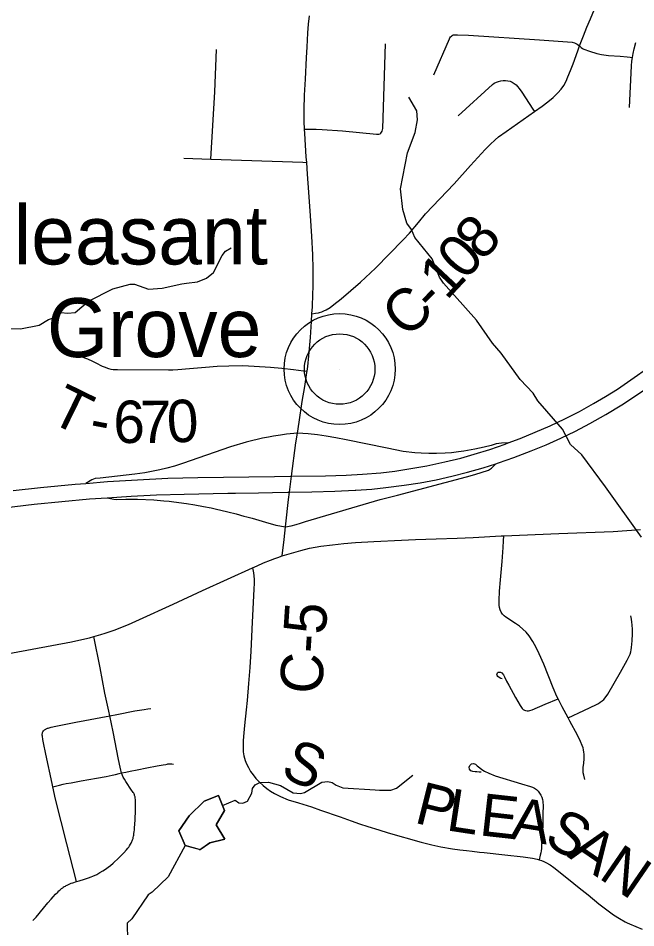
# Model space of a CAD drawing. Extents: x 0 to 34, y 0 to 22.
# Drawn here: x 2.781 to 3.609, y 15.425 to 16.645 of the extents above; entities that cross this region are included whole.
import ezdxf

# ---------------------------------------------------------------- set-up
doc = ezdxf.new("R2010")
doc.units = 0
for name, color, linetype in [('GM_X_County_Road', 7, 'Continuous'), ('GM_X_County_Road_Text', 7, 'Continuous'), ('GM_X_Interchange_Ramps', 7, 'Continuous'), ('GM_X_Interstate_Route', 7, 'Continuous'), ('GM_X_Minor_Lake', 7, 'Continuous'), ('GM_X_Minor_River', 7, 'Continuous'), ('GM_X_State_Route', 7, 'Continuous'), ('GM_X_Township_Road', 7, 'Continuous'), ('GM_X_Township_Road_Text', 7, 'Continuous'), ('GM_X_Unincorporated', 7, 'Continuous'), ('GM_X_Unincorporated_Location', 7, 'Continuous'), ('GM_X_Unincorporated_Text', 7, 'Continuous'), ('GM_X_US_Route', 7, 'Continuous')]:
    doc.layers.add(name, color=color, linetype=linetype)

msp = doc.modelspace()

# ---------------------------------------------------------------- linework, layer by layer
at = {"layer": 'GM_X_County_Road'}
for points in [[(3.533, 16.6075), (3.5384, 16.6211), (3.5428, 16.6327), (3.5477, 16.644), (3.5534, 16.6568)], [(3.4726, 16.5196), (3.4829, 16.5269), (3.4908, 16.5327), (3.4977, 16.5382), (3.5042, 16.5447), (3.5086, 16.5496), (3.5121, 16.5545), (3.515, 16.5603), (3.5176, 16.566), (3.521, 16.5746), (3.5244, 16.5833), (3.5309, 16.6008), (3.533, 16.6075)], [(3.1745, 16.2485), (3.1793, 16.2491), (3.1834, 16.2497), (3.1847, 16.25), (3.1877, 16.2511), (3.1906, 16.2523), (3.1934, 16.2537), (3.1987, 16.257), (3.2038, 16.2607), (3.2136, 16.2684), (3.2266, 16.2796), (3.2395, 16.2908), (3.2597, 16.3097), (3.2968, 16.3473), (3.3051, 16.3565), (3.3171, 16.3708), (3.3268, 16.3824), (3.3458, 16.4026), (3.365, 16.4228), (3.3871, 16.4473), (3.4068, 16.4688), (3.4132, 16.4754), (3.4199, 16.4817), (3.4247, 16.4855), (3.4346, 16.4929), (3.4726, 16.5196)], [(3.0949, 15.9076), (3.0959, 15.9011), (3.0965, 15.8968), (3.0969, 15.8922), (3.0971, 15.8872), (3.0967, 15.8793), (3.0942, 15.8349), (3.0925, 15.7958), (3.0912, 15.7741), (3.0896, 15.7524), (3.0878, 15.7299), (3.0865, 15.7173), (3.0842, 15.6961), (3.083, 15.6866), (3.0822, 15.6762), (3.0821, 15.6655), (3.0823, 15.6611), (3.0832, 15.6555), (3.0848, 15.6493), (3.0866, 15.6447), (3.0892, 15.6398), (3.0923, 15.6346), (3.0955, 15.6303), (3.0994, 15.6253), (3.104, 15.6205), (3.1091, 15.6157), (3.1138, 15.6118), (3.1191, 15.6081), (3.1241, 15.605), (3.1324, 15.6009), (3.1427, 15.5968), (3.1566, 15.5925), (3.1738, 15.5871), (3.1859, 15.5829), (3.2124, 15.5736), (3.2269, 15.5686), (3.2382, 15.5646), (3.2494, 15.5607), (3.264, 15.5562), (3.2766, 15.5523), (3.321, 15.5399), (3.3353, 15.5363), (3.3472, 15.5336), (3.3629, 15.531), (3.3729, 15.5296), (3.3814, 15.5285), (3.3893, 15.5276), (3.3992, 15.5265), (3.4053, 15.5259), (3.4331, 15.523), (3.4578, 15.5202), (3.4701, 15.5182), (3.4762, 15.5169), (3.479, 15.5161)], [(3.479, 15.5161), (3.4823, 15.5151), (3.4852, 15.514), (3.4881, 15.5127), (3.4936, 15.5096), (3.4988, 15.506), (3.5182, 15.4904), (3.5327, 15.4788), (3.5448, 15.469), (3.5592, 15.4573), (3.5714, 15.4477), (3.5788, 15.4423), (3.5865, 15.4373), (3.5945, 15.4329), (3.5972, 15.4317), (3.6001, 15.4304), (3.6172, 15.4233)]]:
    msp.add_lwpolyline(points, dxfattribs=at)
at = {"layer": 'GM_X_Interchange_Ramps'}
for points in [[(3.155, 16.0883), (3.1402, 16.087), (3.1323, 16.0857), (3.1228, 16.0842), (3.1161, 16.083), (3.1082, 16.0814), (3.101, 16.0799), (3.095, 16.0784), (3.0864, 16.0762), (3.0655, 16.07), (3.0008, 16.0474), (2.9904, 16.0442), (2.9799, 16.0414), (2.9705, 16.0391), (2.9617, 16.0373), (2.9506, 16.0353), (2.9371, 16.0334), (2.8906, 16.0281), (2.8838, 16.0275), (2.8795, 16.0256), (2.8712, 16.021)], [(3.4374, 16.0751), (3.4284, 16.0749), (3.4216, 16.0738), (3.4145, 16.0718), (3.4052, 16.0694), (3.3929, 16.0668), (3.3781, 16.0642), (3.3708, 16.0632), (3.3617, 16.0621), (3.3531, 16.0614), (3.3414, 16.061), (3.331, 16.061), (3.321, 16.0613), (3.3123, 16.0621), (3.2968, 16.0639), (3.2753, 16.068), (3.2204, 16.0795), (3.2066, 16.0821), (3.1937, 16.0843), (3.182, 16.0859), (3.1693, 16.0873), (3.155, 16.0883)], [(3.1388, 15.9628), (3.1467, 15.9639), (3.1535, 15.9658), (3.159, 15.9674), (3.1659, 15.9697), (3.2355, 15.9904), (3.266, 15.9992), (3.2891, 16.0052), (3.3817, 16.0297), (3.3927, 16.033), (3.4112, 16.0386), (3.4152, 16.0414), (3.421, 16.0472)], [(2.9001, 16.0016), (2.9091, 15.9998), (2.9128, 15.9993), (2.9248, 15.9996), (2.9407, 15.9996), (2.9623, 15.9987), (2.9761, 15.9977), (2.983, 15.997), (2.9894, 15.9962), (3.0064, 15.9938), (3.0173, 15.992), (3.0292, 15.9899), (3.0392, 15.9881), (3.0466, 15.9864), (3.0524, 15.985), (3.0615, 15.9829), (3.0727, 15.9801), (3.0833, 15.9772), (3.0873, 15.9761)], [(3.0873, 15.9761), (3.0943, 15.9742), (3.1124, 15.9689), (3.1261, 15.965), (3.1388, 15.9628)]]:
    msp.add_lwpolyline(points, dxfattribs=at)
at = {"layer": 'GM_X_Interstate_Route'}
for points in [[(2.7738, 16.0115), (2.8108, 16.0155), (2.8572, 16.0199), (2.8712, 16.021), (2.9005, 16.0233), (2.9408, 16.0259), (2.9812, 16.0278), (3.0215, 16.0288), (3.1241, 16.0303), (3.1472, 16.0306), (3.1924, 16.0311), (3.2204, 16.0319), (3.2421, 16.0332), (3.2669, 16.0353), (3.2855, 16.0375), (3.307, 16.0407), (3.3284, 16.0446), (3.3528, 16.0497), (3.3739, 16.0549), (3.3919, 16.0599), (3.4127, 16.0664), (3.4333, 16.0735), (3.4374, 16.0751), (3.4537, 16.0812), (3.4738, 16.0894), (3.4938, 16.0982), (3.5135, 16.1075), (3.5329, 16.1173), (3.552, 16.1279), (3.568, 16.1374), (3.5838, 16.1474), (3.6019, 16.1596), (3.6272, 16.1775)], [(3.2322, 16.0117), (3.2332, 16.0118), (3.2549, 16.0133), (3.2734, 16.0152), (3.298, 16.0184), (3.3195, 16.0218), (3.3408, 16.0258), (3.362, 16.0305), (3.383, 16.0358), (3.4039, 16.0418), (3.421, 16.0472), (3.4246, 16.0484), (3.4451, 16.0556), (3.4683, 16.0644), (3.4884, 16.0728), (3.5082, 16.0817), (3.5277, 16.0911), (3.5469, 16.1013), (3.5685, 16.1135), (3.5897, 16.1264), (3.608, 16.1382), (3.626, 16.1504)], [(2.6635, 15.9747), (2.6664, 15.9752), (2.7094, 15.9816), (2.7464, 15.9865), (2.8019, 15.993), (2.839, 15.9968), (2.8762, 16), (2.9001, 16.0016), (2.932, 16.0038), (2.9661, 16.0055), (3.0034, 16.0067), (3.0619, 16.0077)], [(3.0619, 16.0077), (3.0718, 16.0079), (3.1028, 16.0084), (3.1214, 16.0088), (3.1423, 16.0092)], [(3.1423, 16.0092), (3.1444, 16.0093), (3.1742, 16.0098), (3.2053, 16.0105), (3.2322, 16.0117)]]:
    msp.add_lwpolyline(points, dxfattribs=at)
at = {"layer": 'GM_X_Minor_Lake'}
for points in [[(3.0377, 15.5389), (3.0577, 15.5438), (3.046, 15.5632), (3.0573, 15.5822), (3.0494, 15.6023), (3.0301, 15.5947), (3.01, 15.5753), (2.996, 15.5552), (3.0044, 15.5355), (3.0247, 15.5299)], [(3.0237, 15.5302), (3.0044, 15.5355), (2.996, 15.5552), (3.01, 15.5753), (3.0301, 15.5947), (3.0494, 15.6023), (3.0573, 15.5822), (3.046, 15.5632), (3.0577, 15.5438), (3.0377, 15.5389), (3.0238, 15.5292)], [(3.0247, 15.5299), (3.0377, 15.5389)]]:
    msp.add_lwpolyline(points, dxfattribs=at)
at = {"layer": 'GM_X_Minor_River'}
for points in [[(3.6161, 15.9486), (3.5681, 16.0163), (3.5364, 16.0594), (3.5212, 16.073), (3.5102, 16.0938), (3.4774, 16.1316), (3.471, 16.1418), (3.4535, 16.1604), (3.4283, 16.1955), (3.4165, 16.2088), (3.3952, 16.2398), (3.3507, 16.2893), (3.3453, 16.2976), (3.3354, 16.3222), (3.3122, 16.3506), (3.3079, 16.3612), (3.3018, 16.3699), (3.2961, 16.3884), (3.2933, 16.4158), (3.3025, 16.464), (3.3126, 16.4914), (3.3159, 16.5085), (3.3151, 16.5203), (3.3044, 16.5388)], [(2.7703, 16.2288), (2.7839, 16.2281), (2.8089, 16.2332), (2.8213, 16.2409), (2.8307, 16.2439), (2.8383, 16.2501), (2.847, 16.249), (2.8572, 16.2502), (2.8749, 16.2654), (2.9077, 16.2816), (2.9308, 16.2881), (2.9364, 16.2882), (2.9554, 16.2814), (2.9735, 16.2827), (3, 16.2885), (3.0064, 16.2893), (3.0212, 16.2913), (3.0329, 16.2959), (3.0427, 16.3039), (3.0543, 16.3264), (3.0584, 16.3321), (3.066, 16.3367)], [(3.0545, 15.5892), (3.0716, 15.596), (3.0766, 15.5926), (3.0819, 15.5923), (3.0879, 15.5946), (3.0939, 15.6056), (3.0946, 15.6117), (3.0984, 15.6166), (3.1044, 15.6197), (3.1161, 15.6205), (3.1321, 15.6157), (3.1491, 15.6059), (3.159, 15.6052), (3.1643, 15.6064), (3.1876, 15.6202), (3.1956, 15.6213), (3.2016, 15.6199), (3.2069, 15.6161), (3.2157, 15.6127), (3.2592, 15.6099), (3.2652, 15.6096), (3.28, 15.6097), (3.2879, 15.6123), (3.3098, 15.6296)], [(3.0044, 15.5355), (2.9817, 15.4934), (2.9603, 15.4728), (2.955, 15.4693), (2.9332, 15.4369), (2.9268, 15.4312), (2.927, 15.408), (2.9213, 15.3966), (2.8733, 15.3227)]]:
    msp.add_lwpolyline(points, dxfattribs=at)
at = {"layer": 'GM_X_State_Route'}
for points in [[(3.155, 16.0883), (3.1572, 16.103), (3.1615, 16.1308), (3.1647, 16.151), (3.1663, 16.1602), (3.1677, 16.1697), (3.1679, 16.1712), (3.1688, 16.1777), (3.1702, 16.1918), (3.1723, 16.2164), (3.1738, 16.2381), (3.1745, 16.2485), (3.1751, 16.2576), (3.1756, 16.2747), (3.1759, 16.2845), (3.1759, 16.2957), (3.1759, 16.3086), (3.1756, 16.3274), (3.1743, 16.3524), (3.1725, 16.3796), (3.1701, 16.4113), (3.1685, 16.4354), (3.1674, 16.4514), (3.1668, 16.459), (3.1648, 16.49), (3.1646, 16.4957), (3.1642, 16.5061), (3.1639, 16.5223), (3.1643, 16.5414), (3.1656, 16.5628), (3.1672, 16.5915), (3.168, 16.6063), (3.1684, 16.6153), (3.1689, 16.6253), (3.1697, 16.6365), (3.171, 16.648)], [(3.1427, 15.9954), (3.1431, 15.9994), (3.1444, 16.0093), (3.1472, 16.0306), (3.153, 16.0754), (3.155, 16.0883)], [(3.1344, 15.9237), (3.137, 15.9457), (3.1388, 15.9628), (3.1397, 15.9707), (3.1427, 15.9954)], [(3.0949, 15.9076), (3.1011, 15.9105), (3.1097, 15.9142), (3.1188, 15.9179), (3.1246, 15.9202), (3.1288, 15.9217), (3.1344, 15.9237)], [(2.8822, 15.8155), (2.8915, 15.8181), (2.8973, 15.82), (2.9109, 15.8247), (2.9182, 15.8275), (2.9284, 15.8317), (2.9433, 15.8383), (2.9884, 15.859), (3.0278, 15.8771), (3.0949, 15.9076)], [(2.6781, 15.7771), (2.6907, 15.7789), (2.773, 15.7937), (2.8522, 15.8086), (2.862, 15.8106), (2.8764, 15.814), (2.8822, 15.8155)]]:
    msp.add_lwpolyline(points, dxfattribs=at)
at = {"layer": 'GM_X_Township_Road'}
msp.add_line((3.0029, 16.457), (3.0389, 16.4555), dxfattribs=at)
for points in [[(3.338, 16.5689), (3.3588, 16.617), (3.3594, 16.6183), (3.3603, 16.6196), (3.3613, 16.6208), (3.3625, 16.6217), (3.3639, 16.6223), (3.3654, 16.6226), (3.3694, 16.6225), (3.3841, 16.6218), (3.4795, 16.6157), (3.5231, 16.6124), (3.5264, 16.6117), (3.5299, 16.6101), (3.533, 16.6075)], [(3.0389, 16.4555), (3.0442, 16.546), (3.0466, 16.6027)], [(3.1646, 16.4957), (3.1693, 16.4958), (3.1803, 16.4959), (3.1882, 16.4956), (3.2153, 16.4935), (3.2612, 16.4893), (3.2628, 16.4893), (3.2643, 16.4893), (3.2658, 16.4897), (3.267, 16.4906), (3.2679, 16.4917), (3.2687, 16.4932), (3.2691, 16.495), (3.2693, 16.4968), (3.2732, 16.6103)], [(3.533, 16.6075), (3.5352, 16.6053), (3.537, 16.6042), (3.5388, 16.6033), (3.5464, 16.6004), (3.5565, 16.5972), (3.5626, 16.596), (3.5657, 16.5955), (3.5719, 16.5949), (3.5877, 16.5938), (3.597, 16.5931), (3.6008, 16.5926), (3.604, 16.592)], [(3.604, 16.592), (3.605, 16.5975), (3.6063, 16.6037), (3.6084, 16.6123)], [(3.5999, 16.525), (3.6028, 16.5809), (3.6033, 16.5871), (3.604, 16.592)], [(3.3703, 16.5139), (3.4163, 16.5559), (3.4189, 16.5576), (3.4217, 16.559), (3.4247, 16.56), (3.4277, 16.5608), (3.4308, 16.5613), (3.4339, 16.5613), (3.437, 16.5609), (3.4401, 16.5601), (3.4429, 16.5588), (3.4456, 16.5572), (3.448, 16.5552), (3.4502, 16.5529), (3.4522, 16.5505), (3.4559, 16.5455), (3.4707, 16.5226), (3.4726, 16.5196)], [(3.0389, 16.4555), (3.1622, 16.4515), (3.1674, 16.4514)], [(2.8648, 16.191), (2.8735, 16.1878), (2.8801, 16.1848), (2.8848, 16.1826), (2.8931, 16.1783), (2.8959, 16.1771), (2.9017, 16.175), (2.9047, 16.1742), (2.9078, 16.1738), (2.914, 16.1735), (2.9823, 16.1732), (2.988, 16.1733), (2.9947, 16.1737), (3.0102, 16.175), (3.0319, 16.1769), (3.0474, 16.1779), (3.063, 16.1785), (3.0816, 16.1789), (3.0971, 16.1783), (3.1188, 16.1769), (3.1343, 16.1754), (3.1497, 16.1737), (3.163, 16.1719), (3.1679, 16.1712)], [(3.5043, 15.7322), (3.5028, 15.7352), (3.4978, 15.7466), (3.4851, 15.7783), (3.4791, 15.7926), (3.4752, 15.8009), (3.4707, 15.809), (3.4655, 15.8167), (3.4617, 15.8214), (3.4573, 15.8256), (3.4526, 15.8295), (3.4475, 15.833), (3.4344, 15.8414), (3.4319, 15.8434), (3.4297, 15.8457), (3.4279, 15.8484), (3.4266, 15.8514), (3.4257, 15.8545), (3.4253, 15.8577), (3.4252, 15.8639), (3.426, 15.8763), (3.4273, 15.8917), (3.4295, 15.9164), (3.4309, 15.9349), (3.4312, 15.9441), (3.4315, 15.9506)], [(3.5177, 15.7066), (3.5389, 15.7166), (3.5557, 15.7244), (3.5584, 15.7258), (3.5609, 15.7274), (3.5633, 15.7292), (3.5655, 15.7312), (3.5675, 15.7334), (3.5709, 15.7384), (3.5882, 15.7676), (3.5972, 15.7837), (3.5998, 15.7892), (3.6008, 15.792), (3.6017, 15.7949), (3.6023, 15.7979), (3.6028, 15.8008), (3.6036, 15.8099), (3.6042, 15.8191), (3.6043, 15.8252), (3.6039, 15.8312), (3.6034, 15.8349), (3.6028, 15.8389), (3.6018, 15.8433)], [(2.9036, 15.7093), (2.9023, 15.7155), (2.897, 15.7398), (2.8906, 15.7734), (2.8822, 15.8155)], [(3.4294, 15.7588), (3.4275, 15.7595), (3.4256, 15.7605), (3.4235, 15.7621), (3.4227, 15.7633), (3.4225, 15.7645), (3.4227, 15.7656), (3.4231, 15.7668), (3.4241, 15.7676), (3.4256, 15.7679), (3.4273, 15.7678), (3.4292, 15.7667), (3.431, 15.7641), (3.4325, 15.7614), (3.4353, 15.7558), (3.4384, 15.7503), (3.4475, 15.7339), (3.4537, 15.7229), (3.4552, 15.7204), (3.4563, 15.719), (3.4578, 15.7178), (3.4594, 15.7168), (3.4609, 15.7163), (3.4628, 15.7158), (3.4646, 15.716), (3.4666, 15.7165), (3.4696, 15.7175), (3.487, 15.7247), (3.5043, 15.7322)], [(3.5177, 15.7066), (3.5097, 15.7213), (3.5043, 15.7322)], [(2.9036, 15.7093), (2.9128, 15.7111), (2.9372, 15.7158), (2.9433, 15.7169), (2.9494, 15.7178), (2.9543, 15.7185), (2.9587, 15.7191)], [(2.8146, 15.6891), (2.8155, 15.6899), (2.8161, 15.6904), (2.8168, 15.6909), (2.8176, 15.6914), (2.8184, 15.6918), (2.819, 15.6921), (2.8199, 15.6925), (2.8209, 15.6928), (2.8221, 15.6932), (2.8234, 15.6935), (2.8249, 15.6939), (2.8311, 15.6953), (2.8401, 15.6971), (2.8581, 15.7007), (2.8702, 15.703), (2.8916, 15.7068), (2.9036, 15.7093)], [(2.9193, 15.6327), (2.9183, 15.6362), (2.9173, 15.6402), (2.9153, 15.6506), (2.9082, 15.6879), (2.9036, 15.7093)], [(3.5401, 15.6237), (3.5387, 15.6298), (3.5382, 15.633), (3.5381, 15.6361), (3.5382, 15.6401), (3.5387, 15.6456), (3.5392, 15.6516), (3.5394, 15.6547), (3.5394, 15.6577), (3.5391, 15.6607), (3.5386, 15.6636), (3.5378, 15.6665), (3.5368, 15.6693), (3.5343, 15.6749), (3.5303, 15.6831), (3.5201, 15.7022), (3.5177, 15.7066)], [(2.8272, 15.6142), (2.8262, 15.6186), (2.8179, 15.6578), (2.8147, 15.6732), (2.8139, 15.6774), (2.8132, 15.682), (2.813, 15.6831), (2.8129, 15.6843), (2.813, 15.6853), (2.8131, 15.6861), (2.8133, 15.6868), (2.8138, 15.6878), (2.8146, 15.6891)], [(2.9193, 15.6327), (2.925, 15.6339), (2.9309, 15.6351), (2.9402, 15.6369), (2.953, 15.6393), (2.9672, 15.642), (2.9751, 15.6436), (2.9785, 15.6442), (2.9803, 15.6446), (2.9812, 15.6447), (2.9824, 15.6448), (2.983, 15.6449), (2.9838, 15.6449), (2.9847, 15.6449), (2.9857, 15.6448), (2.9868, 15.6447), (2.9888, 15.6444)], [(3.4015, 15.6337), (3.3985, 15.6339), (3.3954, 15.6342), (3.3932, 15.6343), (3.3902, 15.6345), (3.3875, 15.6356), (3.3855, 15.6378), (3.3851, 15.6405), (3.3861, 15.6427), (3.3882, 15.6447), (3.3908, 15.6455), (3.3936, 15.6443), (3.396, 15.6424), (3.4033, 15.6366), (3.4059, 15.6349), (3.4114, 15.6322), (3.42, 15.6288), (3.4554, 15.6179), (3.4673, 15.6146), (3.4702, 15.6135), (3.4729, 15.6121), (3.4754, 15.6103), (3.4776, 15.6081), (3.4795, 15.6056), (3.4812, 15.603), (3.4824, 15.6002), (3.4833, 15.5972), (3.4838, 15.5942), (3.4842, 15.588), (3.4841, 15.5788), (3.484, 15.5672), (3.4833, 15.5506), (3.4823, 15.5356), (3.482, 15.5313), (3.4816, 15.5284), (3.4811, 15.5255), (3.4804, 15.5223), (3.479, 15.5161)], [(2.8272, 15.6142), (2.836, 15.6164), (2.8408, 15.6174), (2.8451, 15.6183), (2.8515, 15.6194), (2.8649, 15.6219), (2.8858, 15.6256), (2.8985, 15.6279), (2.9065, 15.6295), (2.9112, 15.6304), (2.916, 15.6318), (2.9193, 15.6327)], [(2.8589, 15.4871), (2.8626, 15.4882), (2.8694, 15.4904), (2.8748, 15.4922), (2.8786, 15.4935), (2.8806, 15.4944), (2.8859, 15.4967), (2.8901, 15.499), (2.894, 15.5013), (2.8977, 15.5037), (2.9012, 15.5062), (2.9044, 15.5087), (2.908, 15.5118), (2.9156, 15.5189), (2.9221, 15.5256), (2.9259, 15.5297), (2.9275, 15.5316), (2.9289, 15.5333), (2.93, 15.5348), (2.9314, 15.5372), (2.9322, 15.5385), (2.9327, 15.5395), (2.9332, 15.5406), (2.9336, 15.5417), (2.9341, 15.5429), (2.9346, 15.5447), (2.9349, 15.5461), (2.9353, 15.5478), (2.9355, 15.5494), (2.9359, 15.5516), (2.9361, 15.5539), (2.9364, 15.5563), (2.9366, 15.5596), (2.9369, 15.5635), (2.9373, 15.5703), (2.9379, 15.5822), (2.9381, 15.5878), (2.9381, 15.5909), (2.938, 15.5927), (2.9379, 15.5951), (2.9378, 15.597), (2.9376, 15.599), (2.9373, 15.6007), (2.9368, 15.6024), (2.9365, 15.6034), (2.936, 15.6045), (2.9355, 15.6055), (2.9349, 15.6064), (2.9341, 15.6077), (2.9328, 15.6096), (2.9251, 15.6212), (2.923, 15.6243), (2.9215, 15.627), (2.9204, 15.6294), (2.9193, 15.6327)], [(2.8589, 15.4871), (2.8457, 15.5377), (2.8309, 15.5975), (2.8272, 15.6142)], [(2.8004, 15.4347), (2.8047, 15.4394), (2.8147, 15.4515), (2.8204, 15.4583), (2.8247, 15.4632), (2.8276, 15.4666), (2.8309, 15.4699), (2.8337, 15.473), (2.8353, 15.4746), (2.8365, 15.4757), (2.8377, 15.4767), (2.8388, 15.4776), (2.8398, 15.4783), (2.8404, 15.4788), (2.8412, 15.4794), (2.8425, 15.4802), (2.8439, 15.481), (2.8451, 15.4817), (2.8465, 15.4824), (2.8481, 15.4831), (2.8492, 15.4836), (2.8506, 15.4842), (2.8519, 15.4847), (2.8541, 15.4855), (2.8589, 15.4871)]]:
    msp.add_lwpolyline(points, dxfattribs=at)
at = {"layer": 'GM_X_Unincorporated'}
for radius in [0.0744, 0.0472]:
    msp.add_circle((3.2116, 16.1742), radius, dxfattribs=at)
at = {"layer": 'GM_X_Unincorporated_Location'}
msp.add_line((3.2116, 16.1742), (3.2116, 16.1742), dxfattribs=at)
at = {"layer": 'GM_X_US_Route'}
for points in [[(3.4315, 15.9506), (3.5054, 15.9537), (3.578, 15.9566), (3.6148, 15.9591)], [(3.1344, 15.9237), (3.1594, 15.9311), (3.1713, 15.9339), (3.1865, 15.9366), (3.2019, 15.9387), (3.2173, 15.9402), (3.2327, 15.9415), (3.2575, 15.9431), (3.2947, 15.9448), (3.3132, 15.9455), (3.3411, 15.9465), (3.369, 15.9477), (3.3906, 15.9485), (3.4279, 15.9504), (3.4315, 15.9506)], [(3.0949, 15.9076), (3.1011, 15.9105), (3.1097, 15.9142), (3.1188, 15.9179), (3.1246, 15.9202), (3.1288, 15.9217), (3.1344, 15.9237)], [(2.8822, 15.8155), (2.8915, 15.8181), (2.8973, 15.82), (2.9109, 15.8247), (2.9182, 15.8275), (2.9284, 15.8317), (2.9433, 15.8383), (2.9884, 15.859), (3.0278, 15.8771), (3.0949, 15.9076)], [(2.6781, 15.7771), (2.6907, 15.7789), (2.773, 15.7937), (2.8522, 15.8086), (2.862, 15.8106), (2.8764, 15.814), (2.8822, 15.8155)]]:
    msp.add_lwpolyline(points, dxfattribs=at)

# ---------------------------------------------------------------- texts
at = {"layer": 'GM_X_County_Road_Text'}
for s, height, rotation, p in [('8', 0.0568, 47.9953, (3.4031, 16.3176)), ('0', 0.0568, 47.7953, (3.3794, 16.2916)), ('1', 0.0568, 46.9053, (3.3548, 16.2653)), ('C', 0.0568, 42.8828, (3.3012, 16.2138)), ('-', 0.0568, 45.6111, (3.3376, 16.2476)), ('C-5', 0.05682, 86.339, (3.1877, 15.7374)), ('S', 0.0568, 336.024, (3.1304, 15.6289)), ('P', 0.0568, 345.981, (3.3102, 15.5664)), ('L', 0.0568, 351.3002, (3.3531, 15.556)), ('E', 0.0568, 353.6141, (3.3976, 15.5492)), ('A', 0.0568, 351.0168, (3.4391, 15.5446)), ('S', 0.0568, 331.1905, (3.4836, 15.5384)), ('A', 0.0568, 325.5481, (3.5159, 15.5207)), ('N', 0.0568, 325.5431, (3.5572, 15.4925))]:
    msp.add_text(s, height=height, rotation=rotation, dxfattribs=at).set_placement(p)
at = {"layer": 'GM_X_Township_Road_Text'}
for s, rotation, p in [('T', 333.9026, (2.8201, 16.1046)), ('6', 359.7633, (2.9082, 16.0752)), ('7', 0.2592, (2.9437, 16.0751)), ('0', 2.7472, (2.9814, 16.0753)), ('-', 349.046, (2.8738, 16.0808))]:
    msp.add_text(s, height=0.0568, rotation=rotation, dxfattribs=at).set_placement(p)
at = {"layer": 'GM_X_Unincorporated_Text'}
for s, p in [('Pleasant', (2.7042, 16.3145)), ('Grove', (2.8192, 16.1903))]:
    msp.add_text(s, height=0.07898, rotation=0, dxfattribs=at).set_placement(p)

doc.saveas('drawing.dxf')
